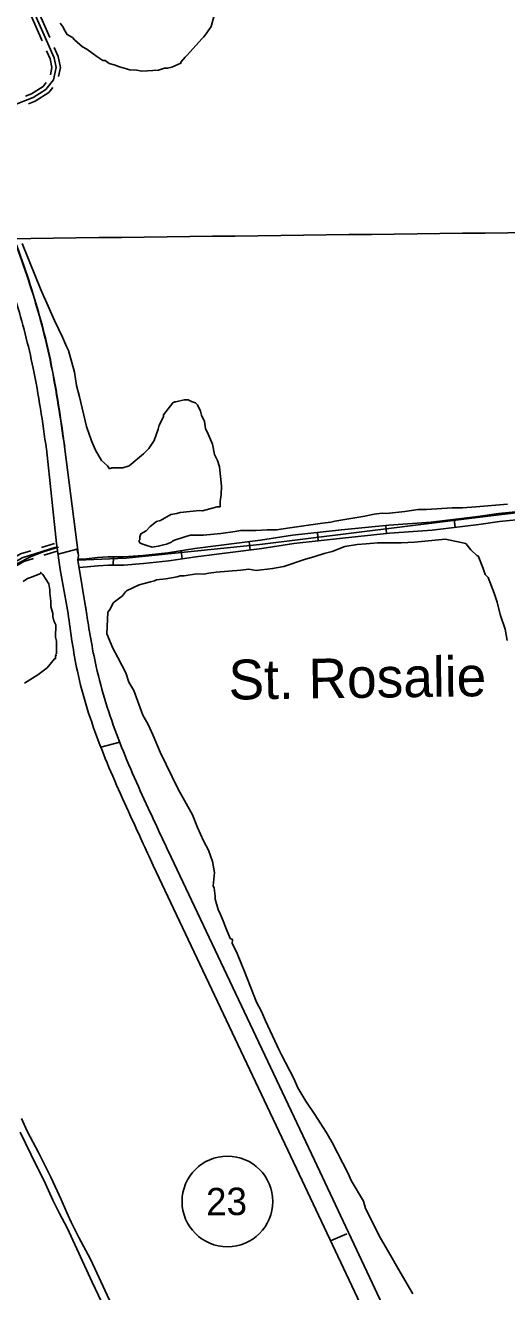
# Model space of a CAD drawing. Extents: x 3694830 to 3732949, y 415201 to 440970.
# Drawn here: x 3711866 to 3713617, y 422992 to 427603 of the extents above; entities that cross this region are included whole.
import ezdxf

# ---------------------------------------------------------------- set-up
doc = ezdxf.new("R2010")
doc.units = 0
for name, color, linetype in [('V-DTCH-CNTR', 7, 'Continuous'), ('V-GRID-MAJR', 7, 'Continuous'), ('V-ROAD-CNTR', 7, 'Continuous'), ('V-ROAD-IDEN', 7, 'Continuous'), ('V-SITE-VEGE', 7, 'Continuous'), ('V-TOPO-GNAM-IDEN', 7, 'Continuous'), ('V-TOPO-SHOR', 7, 'Continuous')]:
    doc.layers.add(name, color=color, linetype=linetype)

msp = doc.modelspace()

# ---------------------------------------------------------------- linework, layer by layer
at = {"layer": 'V-DTCH-CNTR'}
msp.add_lwpolyline([(3707987.034, 422981.787), (3708034.723, 422907.465), (3708041.392, 422902.029), (3708052.162, 422904.62), (3708092.608, 422934.287), (3708330.7660000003, 423108.984), (3708873.06, 423503.072), (3709060.485, 423638.402), (3709106.515, 423671.639), (3709185.441, 423728.62700000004), (3709660.106, 424072.277), (3710010.333, 424323.011), (3710368.667, 424579.048), (3710871.787, 424949.31), (3711077.324, 425096.57), (3711399.159, 425327.41000000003), (3711780.538, 425606.077), (3711791.3570000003, 425614.04000000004), (3711808.941, 425627.315), (3711839.997, 425644.5), (3711884.5330000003, 425666.934), (3711908.812, 425677.46), (3711934.42, 425686.63300000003), (3711986.239, 425702.17600000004)], dxfattribs=at)
at = {"layer": 'V-GRID-MAJR'}
msp.add_spline([(3698983.973, 426676.689), (3704276.781, 426737.893), (3709569.5810000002, 426799.866), (3714862.3710000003, 426862.61), (3720155.153, 426926.124), (3725447.9250000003, 426990.407), (3730740.688, 427055.46), (3730740.6890000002, 427055.46)], degree=3, dxfattribs=at)
at = {"layer": 'V-ROAD-CNTR'}
for p, q in [((3713177.2042770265, 425781.8934032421), (3713180.246576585, 425752.0480616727)), ((3713425.8368018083, 425804.39001099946), (3713429.4472646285, 425774.6080607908)), ((3712928.4518629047, 425755.83819811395), (3712931.7282932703, 425726.0176514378)), ((3712432.28095061, 425689.7055195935), (3712436.7895010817, 425660.04623820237)), ((3712680.445235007, 425722.6602281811), (3712684.252311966, 425692.90277256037)), ((3712185.9825690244, 425667.3809132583), (3712185.7102011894, 425637.38214968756))]:
    msp.add_line(p, q, dxfattribs=at)
for points in [[(3711657.64964574, 427246.6974807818), (3711738.4474841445, 427279.1784158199), (3711831.8492973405, 427316.2103417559), (3711894.471172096, 427339.942294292), (3711940.521079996, 427369.46323525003), (3711968.385024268, 427404.1241659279), (3711977.96400511, 427448.98707620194), (3711970.362020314, 427485.1670038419), (3711873.357214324, 427705.99856217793)], [(3711927.085106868, 427546.38988139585), (3711886.867187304, 427637.9456982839)], [(3711954.551051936, 427558.4558572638), (3711914.333132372, 427650.01167415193)], [(3711986.457988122, 427416.93614030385), (3711993.2969744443, 427448.962076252), (3711984.720991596, 427489.7749946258), (3711970.638019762, 427521.8339305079)], [(3711957.1200467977, 427423.2001277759), (3711962.6310357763, 427449.01207615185), (3711956.0030490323, 427480.55901305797), (3711943.172074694, 427509.7679546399)], [(3711866.222228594, 427345.2782836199), (3711887.6931856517, 427353.41426734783), (3711930.3641003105, 427380.770212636), (3711941.847077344, 427395.05318406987)], [(3711876.85420733, 427317.2243397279), (3711901.24915854, 427326.4703212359), (3711950.678059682, 427358.15625786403), (3711965.2290305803, 427376.2572216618)], [(3711942.357076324, 426061.2948515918), (3711979.47900208, 425716.60754096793), (3711992.12897678, 425621.13773190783), (3712021.566917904, 425461.62905092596)], [(3712008.0049450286, 426069.6508348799), (3712058.62884378, 425671.9246303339), (3712057.1378467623, 425654.8456644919), (3712087.166786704, 425470.35203347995)], [(3712057.1378467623, 425654.8456644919), (3712231.4994980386, 425662.14764988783), (3712718.901523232, 425712.02955012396), (3713579.2828024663, 425818.74333669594), (3714294.828371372, 425903.5501670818), (3714524.5449119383, 425927.50511917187), (3714640.15868071, 425936.554101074), (3714702.917555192, 425928.1411178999), (3714753.387454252, 425898.70117678), (3714785.6683896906, 425842.36128946), (3714822.727315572, 425803.564367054)], [(3712060.2745714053, 425658.9878348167), (3712088.4313100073, 425660.8057102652), (3712128.582459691, 425664.6628080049), (3712167.4640393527, 425667.5490485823), (3712189.2350052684, 425667.35138340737), (3712223.460684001, 425667.04145348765), (3712293.502840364, 425672.67382748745), (3712384.014173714, 425682.3684166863), (3712482.3478033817, 425697.3162546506), (3712721.612927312, 425727.92709557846), (3712838.240002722, 425745.9264791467), (3713016.4682931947, 425765.50870174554), (3713188.2215187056, 425783.0164511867), (3713342.5819215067, 425794.29703025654), (3713512.501085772, 425814.8963134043), (3713587.8528040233, 425825.87174257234), (3713686.828745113, 425835.60755904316)], [(3712062.2074285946, 425629.0501651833), (3712090.832689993, 425630.89828973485), (3712131.127540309, 425634.76919199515), (3712168.439960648, 425637.5389514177), (3712188.962994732, 425637.35261659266), (3712224.5293159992, 425637.0305465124), (3712296.303159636, 425642.8021725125), (3712387.8678262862, 425652.6095833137), (3712486.5061966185, 425667.6037453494), (3712725.805072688, 425698.21890442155), (3712842.1679972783, 425716.1775208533), (3713019.6277068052, 425735.6752982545), (3713190.8364812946, 425753.12754881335), (3713345.4820784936, 425764.4289697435), (3713516.468914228, 425785.1576865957), (3713591.4851959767, 425796.0842574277), (3713689.387254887, 425805.7144409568)], [(3711057.122846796, 425092.33078952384), (3711228.248504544, 425212.558549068), (3711606.8887472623, 425489.803994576), (3711690.7475795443, 425541.9948901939), (3711797.4263661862, 425630.78471261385), (3711854.7512515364, 425664.3866454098), (3711976.5530079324, 425702.30256957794)], [(3711886.163188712, 425689.87459443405), (3711848.6502637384, 425678.19761778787), (3711793.3053744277, 425645.755682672)], [(3711972.0950168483, 425716.6245409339), (3711924.355112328, 425701.76357065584)], [(3711981.010999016, 425687.980598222), (3711933.271094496, 425673.119627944)], [(3711984.73899156, 425676.912620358), (3712052.950855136, 425696.0155821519), (3712057.656845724, 425679.5646150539)], [(3711895.0791708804, 425661.23065172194), (3711860.852239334, 425650.5756730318), (3711808.475344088, 425619.8737344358)], [(3712140.6686797, 424974.10402597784), (3712210.15854072, 424993.0849880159)], [(3712396.470168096, 424573.692826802), (3712917.7871254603, 423470.3990333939), (3713289.607381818, 422680.12461394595), (3713389.273182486, 422467.4760392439)], [(3712331.370298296, 424542.95288828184), (3712852.6602557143, 423439.71609475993), (3713224.4295121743, 422649.5496750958), (3713324.07131289, 422436.95210029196)], [(3712976.1660087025, 423177.21461976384), (3713036.077888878, 423202.0135701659)]]:
    msp.add_lwpolyline(points, dxfattribs=at)
for points in [[(3711704.7995514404, 427131.0317121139), (3711795.7483695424, 426900.94517228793), (3711893.725173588, 426622.3997293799), (3711959.1410427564, 426368.29423759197), (3712008.0049450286, 426069.6508348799)], [(3711705.8335493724, 427131.4407112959), (3711796.7903674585, 426901.33417151), (3711894.7901714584, 426622.72372873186), (3711960.230040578, 426368.523237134), (3712009.101942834, 426069.8308345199)], [(3711638.2356845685, 427103.89776638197), (3711733.637493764, 426877.75621866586), (3711830.245300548, 426603.103767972), (3711894.2051726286, 426354.6522648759), (3711942.58907586, 426058.94785628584)], [(3712021.566917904, 425461.62905092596), (3712055.0858508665, 425250.96347225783), (3712137.1746866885, 424982.6930087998), (3712248.577463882, 424723.75452667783), (3712331.370298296, 424542.95288828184)], [(3712087.166786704, 425470.35203347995), (3712086.9877870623, 425471.69703078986), (3712085.1917906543, 425485.4340033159)], [(3712087.166786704, 425470.35203347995), (3712123.681713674, 425267.7724386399), (3712203.4715540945, 425007.014960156), (3712312.92333519, 424752.61146896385), (3712396.470168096, 424573.692826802)]]:
    msp.add_spline(points, degree=3, dxfattribs=at)
at = {"layer": 'V-ROAD-IDEN'}
msp.add_circle((3712601.0438638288, 423320.0428336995), 164.99967000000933, dxfattribs=at)
at = {"layer": 'V-SITE-VEGE'}
for points in [[(3711992.661, 427610.783), (3712003.733, 427595.742), (3712007.401, 427588.238), (3712018.44, 427569.46400000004), (3712037.015, 427558.092), (3712044.418, 427550.555), (3712074.063, 427524.14400000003), (3712088.938, 427516.54000000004), (3712126.054, 427490.061), (3712148.33, 427474.92), (3712155.801, 427474.855), (3712170.6410000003, 427463.515), (3712189.282, 427459.614), (3712207.89, 427451.977), (3712233.969, 427444.272), (3712245.1410000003, 427440.436), (3712271.286, 427440.205), (3712289.927, 427436.30100000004), (3712349.72, 427439.50200000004), (3712372.197, 427446.773), (3712383.401, 427446.672), (3712398.3740000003, 427450.275), (3712432.123, 427464.914), (3712432.156, 427468.647), (3712447.264, 427487.19), (3712454.801, 427494.593), (3712507.625, 427553.885), (3712515.162, 427561.289), (3712526.4990000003, 427576.128), (3712541.64, 427598.407), (3712553.213, 427639.391)], [(3712443.586, 426239.632), (3712413.6380000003, 426232.429), (3712409.903, 426232.462), (3712402.401, 426228.794), (3712368.383, 426184.275), (3712368.318, 426176.804), (3712353.111, 426147.059), (3712349.2430000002, 426132.151), (3712333.934, 426091.199), (3712314.992, 426061.487), (3712296.15, 426042.979), (3712243.46, 425998.626), (3712220.985, 425991.355), (3712179.898, 425991.724), (3712172.396, 425988.056), (3712165.025, 425999.326), (3712142.782, 426018.20300000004), (3712120.7060000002, 426055.753), (3712106.065, 426089.50200000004), (3712087.859, 426141.957), (3712062.683, 426250.507), (3712051.845, 426291.692), (3712044.808, 426340.314), (3712023.099, 426418.951), (3712015.7630000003, 426433.957), (3712001.122, 426467.704), (3711971.778, 426527.731), (3711938.83, 426602.732), (3711931.494, 426617.738), (3711920.521, 426643.983), (3711902.2460000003, 426688.972), (3711854.759, 426808.925)], [(3713620.543, 425859.319), (3713504.657, 425849.148), (3713456.068, 425845.847), (3713418.719, 425846.181), (3713325.2770000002, 425839.545), (3713295.396, 425839.814), (3713246.775, 425832.777), (3713179.477, 425825.91000000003), (3713164.537, 425826.041), (3713134.6240000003, 425822.57300000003), (3713100.943, 425815.403), (3712992.46, 425797.696), (3712977.487, 425794.096), (3712947.572, 425790.62700000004), (3712827.887, 425773.02), (3712779.268, 425765.983), (3712745.65, 425766.284), (3712704.532, 425762.917), (3712652.24, 425763.384), (3712648.507, 425763.417), (3712629.798, 425759.849), (3712577.4390000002, 425752.84500000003), (3712513.879, 425745.943), (3712465.323, 425746.378), (3712442.847, 425739.107), (3712409.132, 425728.204), (3712401.629, 425724.536), (3712397.86, 425720.835), (3712379.119, 425713.53), (3712364.144, 425709.929), (3712349.171, 425706.329), (3712326.727, 425702.792), (3712304.3850000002, 425710.46400000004), (3712289.478, 425714.333), (3712282.042, 425718.134), (3712278.3740000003, 425725.63800000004), (3712282.142, 425729.338), (3712282.242, 425740.543), (3712286.076, 425751.713), (3712304.852, 425762.753), (3712319.926, 425777.56), (3712342.503, 425796.033), (3712357.4760000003, 425799.634), (3712395.0300000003, 425821.711), (3712417.47, 425825.246), (3712428.707, 425828.881), (3712499.74, 425835.718), (3712510.9450000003, 425835.617), (3712563.369, 425850.09), (3712574.574, 425849.99), (3712574.742, 425868.666), (3712578.7090000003, 425894.778), (3712578.975, 425924.656), (3712572.1410000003, 425995.689), (3712564.8710000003, 426018.166), (3712553.867, 426040.677), (3712546.7290000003, 426078.092), (3712532.09, 426111.841), (3712521.086, 426134.351), (3712517.5840000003, 426160.528), (3712506.58, 426183.038), (3712502.98, 426198.01300000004), (3712491.972, 426220.52400000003), (3712484.571, 426228.059), (3712473.399, 426231.895), (3712458.524, 426239.49700000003), (3712443.586, 426239.632)], [(3712706.592, 424045.522), (3712662.775, 424157.973), (3712651.804, 424184.219), (3712633.5300000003, 424229.205), (3712618.858, 424259.218), (3712618.991, 424274.158), (3712611.557, 424277.96), (3712593.2800000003, 424322.94800000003), (3712585.975, 424341.689), (3712575.004, 424367.934), (3712567.668, 424382.94), (3712556.7970000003, 424420.392), (3712556.898, 424431.596), (3712553.43, 424461.51), (3712549.7600000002, 424469.01300000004), (3712553.93, 424517.53500000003), (3712546.828, 424558.685), (3712532.254, 424599.905), (3712513.879, 424633.68700000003), (3712491.904, 424682.442), (3712473.628, 424727.43), (3712422.174, 424821.271), (3712356.145, 424956.333), (3712330.534, 425016.325), (3712312.227, 425057.57800000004), (3712293.853, 425091.36), (3712261.037, 425181.302), (3712242.63, 425211.348), (3712231.724, 425245.064), (3712202.346, 425301.355), (3712183.971, 425335.137), (3712162.029, 425387.62700000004), (3712166.465, 425466.029), (3712174.034, 425477.168), (3712185.44, 425499.477), (3712204.2490000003, 425514.249), (3712219.289, 425525.32300000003), (3712230.629, 425540.16000000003), (3712234.395, 425543.863), (3712279.416, 425565.871), (3712320.602, 425576.70900000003), (3712335.574, 425580.311), (3712343.078, 425583.979), (3712376.727, 425587.416), (3712417.877, 425594.518), (3712429.117, 425598.152), (3712444.057, 425598.02), (3712488.943, 425605.088), (3712515.09, 425604.855), (3712533.796, 425608.422), (3712559.9760000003, 425611.924), (3712649.682, 425618.593), (3712679.595, 425622.06200000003), (3712705.707, 425618.093), (3712765.534, 425625.027), (3712806.686, 425632.132), (3712881.62, 425657.609), (3712919.0700000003, 425668.48), (3712952.784, 425679.38300000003), (3712982.734, 425686.58400000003), (3713027.719, 425704.863), (3713072.6070000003, 425711.93), (3713106.253, 425715.367), (3713147.373, 425718.734), (3713233.276, 425717.966), (3713281.865, 425721.26900000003), (3713394.0160000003, 425731.47000000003), (3713468.583, 425715.862), (3713487.056, 425693.28500000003), (3713509.267, 425670.675), (3713513, 425670.643), (3713531.2770000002, 425625.654), (3713538.545, 425603.179), (3713549.649, 425591.874), (3713571.561, 425535.64900000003), (3713582.464, 425501.93200000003), (3713593.27, 425457.014), (3713611.4760000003, 425404.556), (3713618.5810000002, 425363.404)], [(3711858.274, 425577.678), (3711873.3140000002, 425588.749), (3711884.554, 425592.384), (3711922.036, 425606.991), (3711922.071, 425610.726), (3711929.472, 425603.19), (3711951.583, 425569.373), (3711955.117, 425546.931), (3711955.017, 425535.726), (3711958.486, 425505.811), (3711958.319, 425487.13800000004), (3711965.554, 425460.925), (3711965.4560000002, 425449.723), (3711969.056, 425434.748)], [(3711969.056, 425434.748), (3711976.392, 425419.74), (3711975.9930000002, 425374.92), (3711979.593, 425359.947), (3711979.194, 425315.126), (3711975.4250000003, 425311.425)], [(3711975.4250000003, 425311.425), (3711979.126, 425307.657), (3711975.3910000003, 425307.69), (3711975.29, 425296.485), (3711971.557, 425296.518), (3711945.111, 425263.13800000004), (3711911.262, 425237.292), (3711862.4390000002, 425207.848)], [(3713276.073, 422983.343), (3713220.884, 423077.217), (3713195.1380000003, 423122.271), (3713158.356, 423186.103), (3713103.3000000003, 423294.91500000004), (3713096.062, 423321.128), (3713051.91, 423396.23), (3713040.938, 423422.473), (3712982.179, 423535.058), (3712960.1040000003, 423572.61), (3712937.994, 423606.424), (3712919.586, 423636.471), (3712886.4050000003, 423685.326), (3712856.958, 423734.148), (3712842.319, 423767.897), (3712798.267, 423854.204), (3712790.931, 423869.20900000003), (3712739.608, 423977.991), (3712724.969, 424011.74), (3712706.592, 424045.522)]]:
    msp.add_lwpolyline(points, dxfattribs=at)
at = {"layer": 'V-TOPO-SHOR'}
for points in [[(3712209.1920000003, 422879.321), (3712102.356, 423109.77400000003), (3712060.778, 423189.466), (3712032.7260000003, 423244.711), (3712015.085, 423281.884), (3711996.463, 423327.528), (3711958.0670000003, 423408.248), (3711913.412, 423498.544), (3711872.87, 423576.11), (3711852.134, 423621.772)], [(3712201.592, 422832.336), (3712109.225, 423025.64400000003), (3712017.9620000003, 423224.231), (3711989.882, 423276.303), (3711966.003, 423325.166), (3711939.045, 423384.632), (3711886.0840000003, 423491.923), (3711846.629, 423572.653)]]:
    msp.add_lwpolyline(points, dxfattribs=at)

# ---------------------------------------------------------------- texts
at = {"layer": 'V-ROAD-IDEN'}
msp.add_text('23', height=100.00008999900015, rotation=0.7811027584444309, dxfattribs=at).set_placement((3712524.1736806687, 423268.99030287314))
at = {"layer": 'V-TOPO-GNAM-IDEN'}
msp.add_text('St. Rosalie', height=144.99971199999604, rotation=0.7811860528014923, dxfattribs=at).set_placement((3712606.2007486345, 425147.490679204))

doc.saveas('drawing.dxf')
